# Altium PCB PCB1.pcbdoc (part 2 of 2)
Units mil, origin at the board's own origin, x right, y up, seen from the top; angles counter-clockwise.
Board outline 2869.57 x 2682.86 mil, 2 copper layers (Top Layer, Bottom Layer); 61 components, 43 nets, 230 pads, 47 vias.
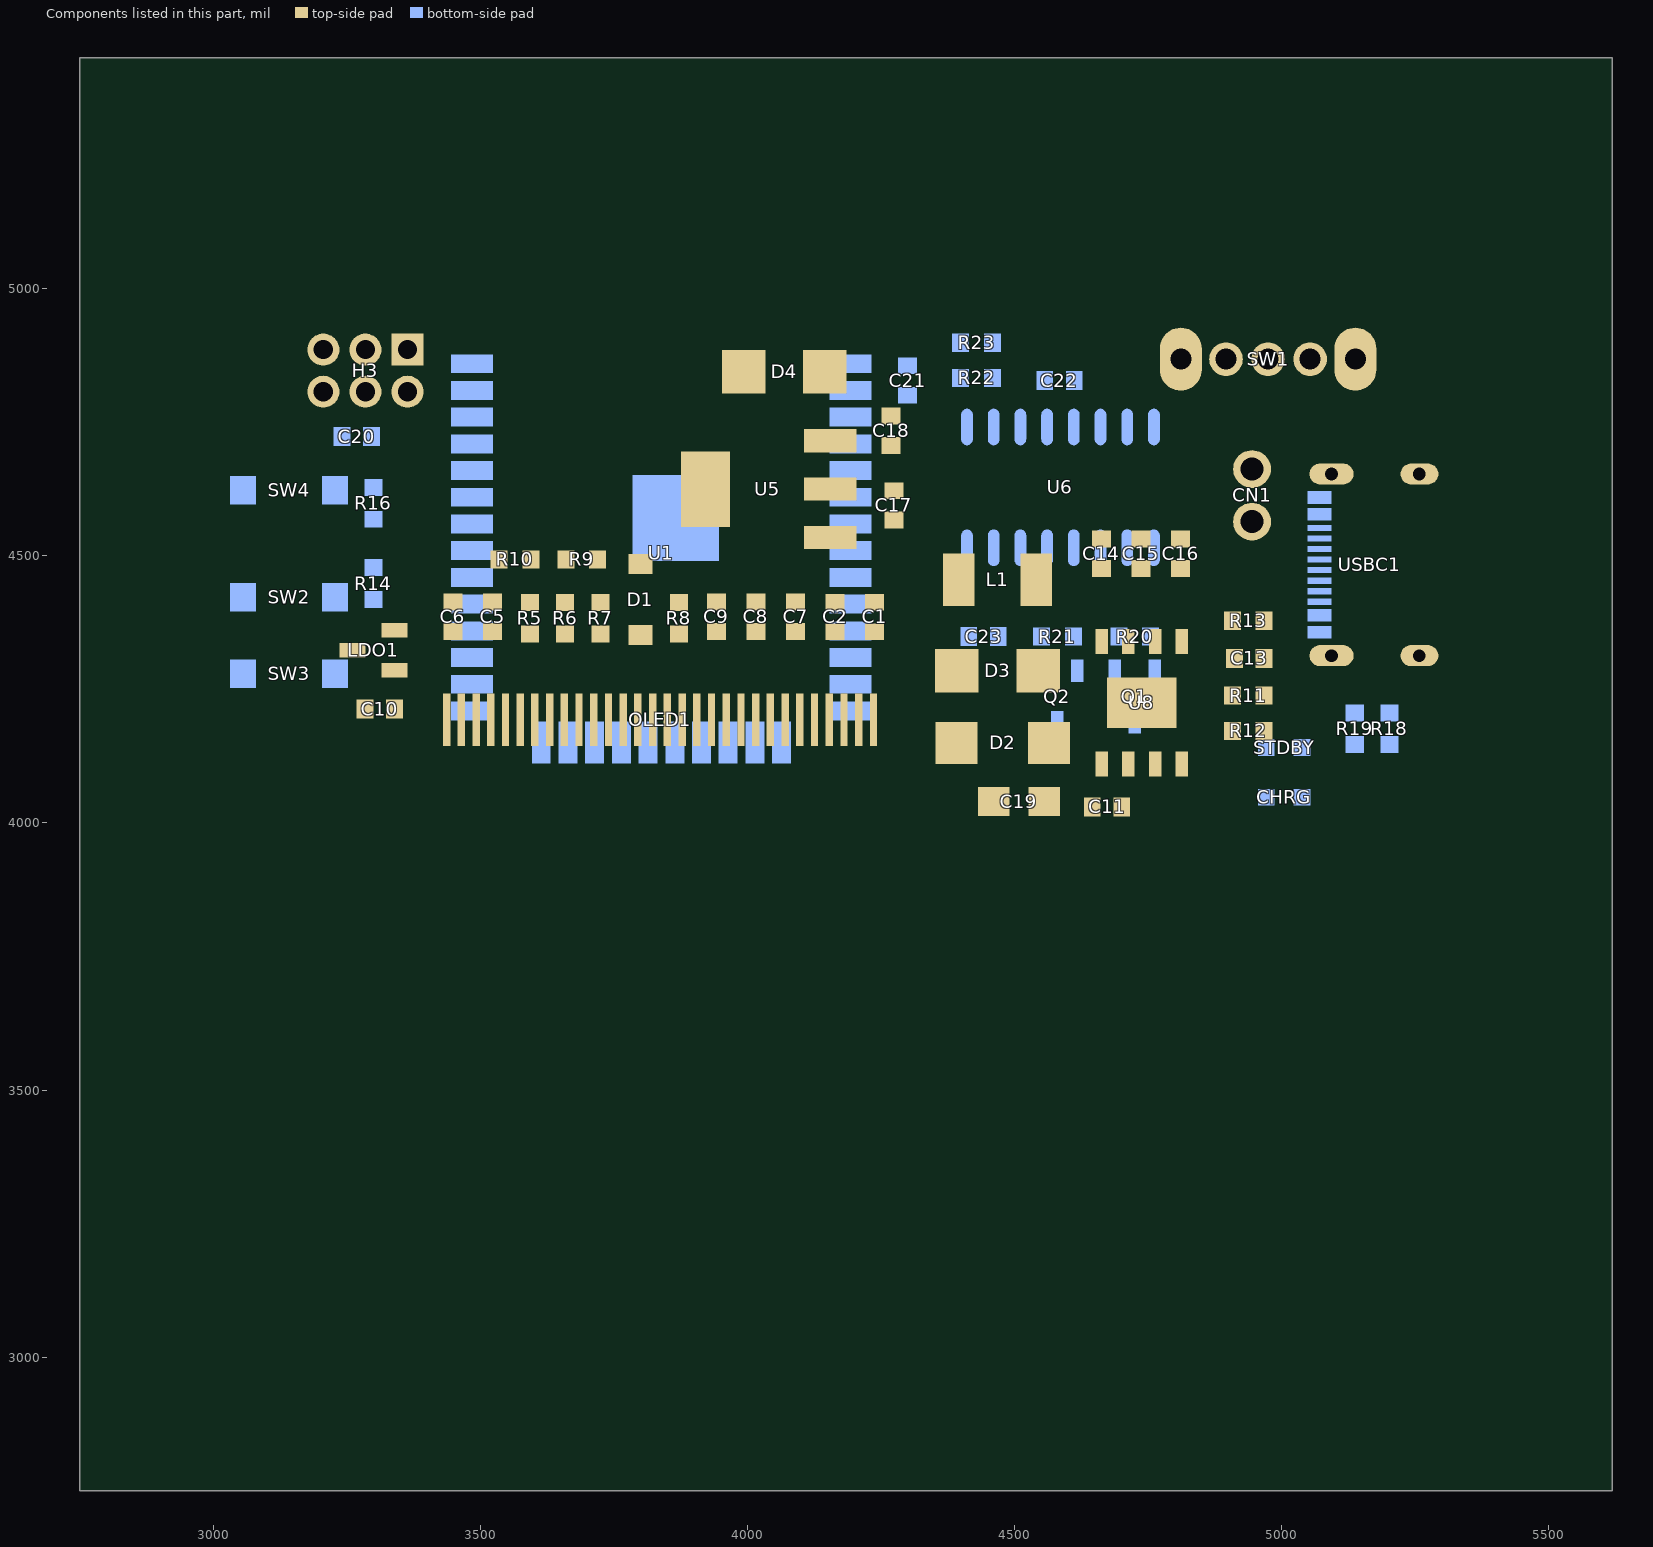
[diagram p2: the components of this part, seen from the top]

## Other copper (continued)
Bottom Layer:
  region net 3V3: 4262.95,4799.79 4262.95,4819.79 cw(c4262.95,5034.18) 4232.95,4821.9 4232.95,4797.68 cw(c4262.95,4585.4)
  region net EN: 4139.21,4758.33 4139.21,4748.33 cw(c4139.21,4727.21) 4154.21,4742.07 4154.21,4765.83 cw(c4139.21,4777.08)
  region net EN: 4247.95,4754.79 4247.95,4764.79 cw(c4247.95,4783.54) 4232.95,4772.29 4232.95,4747.29 cw(c4247.95,4736.04)
  region net IO32: 4143.54,4514.79 4143.54,4504.79 cw(c4143.54,4493.44) 4154.21,4497.29 4154.21,4522.29 cw(c4143.54,4526.13)
  region net IO33: 4143.61,4481.79 4143.61,4467.65 cw(c4118,4442.04) 4154.21,4442.07 4158.5,4477.5 cw(c4154.93,4493.11)
  region net IO2: 3581.54,4155.73 3581.54,4145.73 cw(c3581.54,4126.98) 3596.54,4138.23 3596.54,4163.23 cw(c3581.54,4174.48)
  region net IO0: 3539.29,4204.79 3539.29,4214.79 cw(c3539.29,4233.54) 3524.29,4222.29 3524.29,4197.29 cw(c3539.29,4186.04)
  region net IO0: 3430.55,4214.79 3430.55,4204.79 cw(c3430.55,4186.04) 3445.55,4197.29 3445.55,4222.29 cw(c3430.55,4233.54)
  region net SCL: 3528.82,4431.46 3534.9,4439.52 cw(c3561.42,4466.04) 3524.29,4460.74 3507.6,4442.07 cw(c3502.3,4404.95)
  region net RXD0: 3534.9,4676.15 3532.71,4688.11 cw(c3506.2,4714.63) 3511.5,4677.5 3524.29,4664.06 cw(c3621.68,4589.38)
  region net TXD0: 3536.46,4704.79 3536.46,4714.79 cw(c3536.46,4728.41) 3524.29,4722.29 3524.29,4697.29 cw(c3536.46,4691.17)
  region net $1N4419: 5043.5,4079.07 5033.5,4079.07 cw(c5014.75,4079.07) 5026,4064.07 5051,4064.07 cw(c5062.25,4079.07)
  region net $1N4369: 4940.75,4053.33 4940.75,4043.33 cw(c4940.75,4024.58) 4955.75,4035.83 4955.75,4060.83 cw(c4940.75,4072.08)
  region net 3V3: 3347.01,4558.33 3347.01,4578.33 cw(c3347.01,4653.83) 3317.01,4584.54 3317.01,4552.79 cw(c3347.01,4474.27)
  region net 3V3: 3290,4522.79 3310,4522.79 cw(c3524.39,4522.79) 3312.11,4552.79 3287.89,4552.79 cw(c3075.61,4522.79)
  region net EN: 3267.99,4632.99 3267.99,4622.99 cw(c3267.99,4604.24) 3282.99,4615.49 3282.99,4640.49 cw(c3267.99,4651.74)
  region net EN: 3332.01,4622.99 3332.01,4632.99 cw(c3332.01,4651.74) 3317.01,4640.49 3317.01,4615.49 cw(c3332.01,4604.24)
  region net $1N9758: 4465,4790.13 4455,4788.79 4454.8,4787.52 4450.32,4765.18 4450.27,4764.74 4472.32,4764.74 4472.24,4765.18
  region net $1N9782: 4516.29,4789.57 4506.29,4789.57 4506.23,4789.14 4500.83,4767.36 4500.34,4765.19 4500.27,4764.74 4522.32,4764.74 4522.25,4765.18 4516.85,4786.99 4516.36,4789.14
  region net $1N9477: 4566.29,4789.57 4556.29,4789.57 4556.36,4788.21 4556.53,4786.94 4556.79,4785.74 4557.26,4784.08 4558.22,4781.11 4558.44,4780.21 4558.52,4779.77 4558.57,4779.34 4558.59,4778.91 4558.58,4778.49 4558.53,4778.08 4558.44,4777.66 4558.3,4777.25 4558.12,4776.84 4557.89,4776.43 4557.6,4776.03 4557.26,4775.62 4556.85,4775.21 4556.38,4774.79 4555.85,4774.38 4555.24,4773.96 4567.35,4773.96 4566.74,4774.38 4566.2,4774.79 4565.74,4775.21 4565.33,4775.62 4564.99,4776.03 4564.7,4776.43 4564.47,4776.84 4564.29,4777.25 4564.15,4777.66 4564.06,4778.08 4564.01,4778.49 4564,4778.91 4564.02,4779.34 4564.07,4779.77 4564.24,4780.66 4564.65,4782.05 4565.65,4785.17 4565.94,4786.33 4566.16,4787.57 4566.28,4788.88
  region net D+: 4606.29,4693.27 4616.29,4693.27 4616.23,4694.62 4616.06,4695.89 4615.8,4697.09 4615.33,4698.76 4614.37,4701.72 4614.14,4702.62 4614.07,4703.06 4614.02,4703.49 4614,4703.92 4614.01,4704.34 4614.06,4704.76 4614.15,4705.17 4614.29,4705.58 4614.47,4705.99 4614.7,4706.4 4614.99,4706.81 4615.33,4707.22 4615.74,4707.63 4616.2,4708.04 4616.74,4708.46 4617.35,4708.88 4605.24,4708.88 4605.85,4708.46 4606.38,4708.04 4606.85,4707.63 4607.26,4707.22 4607.6,4706.81 4607.89,4706.4 4608.12,4705.99 4608.3,4705.58 4608.44,4705.17 4608.53,4704.76 4608.58,4704.34 4608.59,4703.92 4608.57,4703.49 4608.52,4703.06 4608.34,4702.18 4607.93,4700.78 4606.94,4697.66 4606.65,4696.5 4606.43,4695.27 4606.31,4693.95
  region net D-: 4656.29,4693.27 4666.29,4693.27 4666.23,4694.62 4666.06,4695.89 4665.8,4697.09 4665.33,4698.76 4664.37,4701.72 4664.14,4702.62 4664.07,4703.06 4664.02,4703.49 4664,4703.92 4664.01,4704.34 4664.06,4704.76 4664.15,4705.17 4664.29,4705.58 4664.47,4705.99 4664.7,4706.4 4664.99,4706.81 4665.33,4707.22 4665.74,4707.63 4666.2,4708.04 4666.74,4708.46 4667.35,4708.88 4655.24,4708.88 4655.85,4708.46 4656.38,4708.04 4656.85,4707.63 4657.26,4707.22 4657.6,4706.81 4657.89,4706.4 4658.12,4705.99 4658.3,4705.58 4658.44,4705.17 4658.53,4704.76 4658.58,4704.34 4658.59,4703.92 4658.57,4703.49 4658.52,4703.06 4658.34,4702.18 4657.93,4700.78 4656.94,4697.66 4656.65,4696.5 4656.43,4695.27 4656.31,4693.95
  region net +5V: 4421.29,4573.2 4401.29,4573.2 4400.27,4538.56 4422.32,4538.56
  region net +5V: 4401.29,4457.27 4421.29,4457.27 4421.26,4457.95 4421.18,4458.66 4421.04,4459.41 4420.62,4461.01 4419.73,4463.59 4416.78,4471 4415.85,4473.73 4415.39,4475.47 4415.23,4476.3 4415.11,4477.1 4415.05,4477.88 4415.05,4478.61 4415.12,4479.32 4415.25,4479.98 4415.46,4480.6 4415.75,4481.17 4416.13,4481.69 4416.59,4482.16 4417.15,4482.57 4405.43,4482.57 4406,4482.16 4406.46,4481.69 4406.84,4481.17 4407.13,4480.6 4407.34,4479.98 4407.47,4479.32 4407.54,4478.61 4407.54,4477.88 4407.48,4477.1 4407.36,4476.3 4406.99,4474.61 4406.46,4472.84 4405.08,4469.14 4402.53,4462.71 4401.97,4461.01 4401.55,4459.41 4401.41,4458.66 4401.32,4457.95
  region net RTS: 4506.29,4467.09 4516.29,4467.09 4516.23,4468.44 4516.06,4469.71 4515.8,4470.91 4515.33,4472.58 4514.37,4475.54 4514.14,4476.44 4514.07,4476.88 4514.02,4477.31 4514,4477.74 4514.01,4478.16 4514.06,4478.58 4514.15,4478.99 4514.29,4479.4 4514.47,4479.81 4514.7,4480.22 4514.99,4480.63 4515.33,4481.04 4515.74,4481.45 4516.2,4481.86 4516.74,4482.28 4517.35,4482.7 4505.24,4482.7 4505.85,4482.28 4506.38,4481.86 4506.85,4481.45 4507.26,4481.04 4507.6,4480.63 4507.89,4480.22 4508.12,4479.81 4508.3,4479.4 4508.44,4478.99 4508.53,4478.58 4508.58,4478.16 4508.59,4477.74 4508.57,4477.31 4508.52,4476.88 4508.34,4476 4507.93,4474.6 4506.94,4471.48 4506.65,4470.32 4506.43,4469.09 4506.31,4467.77
  region net DTR: 4556.29,4467.09 4566.29,4467.09 4566.23,4468.44 4566.06,4469.71 4565.8,4470.91 4565.33,4472.58 4564.37,4475.54 4564.14,4476.44 4564.07,4476.88 4564.02,4477.31 4564,4477.74 4564.01,4478.16 4564.06,4478.58 4564.15,4478.99 4564.29,4479.4 4564.47,4479.81 4564.7,4480.22 4564.99,4480.63 4565.33,4481.04 4565.74,4481.45 4566.2,4481.86 4566.74,4482.28 4567.35,4482.7 4555.24,4482.7 4555.85,4482.28 4556.38,4481.86 4556.85,4481.45 4557.26,4481.04 4557.6,4480.63 4557.89,4480.22 4558.12,4479.81 4558.3,4479.4 4558.44,4478.99 4558.53,4478.58 4558.58,4478.16 4558.59,4477.74 4558.57,4477.31 4558.52,4476.88 4558.34,4476 4557.93,4474.6 4556.94,4471.48 4556.65,4470.32 4556.43,4469.09 4556.31,4467.77
  region net V_USB: 5029.49,4398.84 5029.49,4378.84 cw(c5029.49,4273.3) 5048.96,4377.03 5048.96,4400.65 cw(c5029.49,4504.37)
  region net V_USB: 5034.49,4587.82 5034.49,4567.82 cw(c5034.49,4506.07) 5048.96,4566.1 5048.96,4589.54 cw(c5034.49,4649.56)
  region net D+: 5045,4458.8 5045,4448.8 cw(c5045,4439.7) 5048.96,4447.89 5048.96,4459.7 cw(c5045,4467.9)
  region net D-: 5100.16,4468.49 5100.16,4478.49 cw(c5100.16,4499.36) 5094.23,4479.35 5094.23,4467.63 cw(c5100.16,4447.62)
  region net D+: 5034.47,4498.17 5034.47,4488.17 cw(c5034.47,4371.81) 5048.96,4487.26 5048.96,4499.07 cw(c5034.47,4614.53)
  region net D-: 5033.96,4517.86 5033.96,4507.86 cw(c5033.96,4383.16) 5048.96,4506.95 5048.96,4518.76 cw(c5033.96,4642.55)
  region net D-: 5100.47,4507.86 5100.47,4517.86 cw(c5100.47,4539.79) 5094.23,4518.76 5094.23,4506.95 cw(c5100.47,4485.92)
  region net $1N9366: 5109.23,4527.54 5109.23,4537.54 cw(c5109.23,4668.87) 5094.23,4538.4 5094.23,4526.68 cw(c5109.23,4396.2)
  region net 3V3: 4317.93,4768.7 4332.07,4782.84 ccw(c4323.41,4774.18) 4317.72,4785.02 4282.28,4785.02 cw(c4278.16,4728.92)
  region net $1N9366: 5207.18,4236.76 5197.18,4236.76 cw(c5178.43,4236.76) 5189.68,4221.76 5214.68,4221.76 cw(c5225.93,4236.76)
  region net $1N17323: 5158.54,4220.17 5151.46,4227.24 cw(c5137.85,4240.86) 5135.38,4221.76 5154.19,4205.22 cw(c5169.97,4208.74)
  region net $1N9680: 4693.26,4321.45 4683.26,4321.45 cw(c4663.34,4321.45) 4676.45,4306.45 4700.08,4306.45 cw(c4713.19,4321.45)
  region net RTS: 4740.65,4270.04 4740.65,4255.9 cw(c4761.07,4235.48) 4759.68,4264.33 4751.25,4291.26 cw(c4714.13,4296.56)
  region net EN: 4698.85,4193.14 4698.85,4183.14 cw(c4698.85,4164.39) 4713.85,4175.64 4713.85,4200.64 cw(c4698.85,4211.89)
  region net $1N9678: 4548.26,4321.45 4538.26,4321.45 cw(c4518.34,4321.45) 4531.45,4306.45 4555.08,4306.45 cw(c4568.19,4321.45)
  region net IO0: 4558.25,4172.79 4559.39,4159.79 cw(c4576.98,4142.2) 4577.28,4167.08 4568.85,4194.01 cw(c4531.73,4199.31)
  region net $1N9680: 4683.26,4317.08 4693.26,4317.08 cw(c4712.01,4317.08) 4700.76,4332.08 4682.21,4332.08 cw(c4576.07,4317.08)
  region net DTR: 4733.7,4376.7 4728.84,4367.41 cw(c4702.33,4340.9) 4739.45,4346.2 4754.91,4366.09 cw(c4760.21,4403.22)
  region net DTR: 4779.78,4321.47 4781.81,4333.59 cw(c4808.32,4360.11) 4771.2,4354.8 4758.57,4332.08 cw(c4753.27,4294.95)
  region net $1N9678: 4538.26,4317.08 4548.26,4317.08 cw(c4567.01,4317.08) 4555.76,4332.08 4537.21,4332.08 cw(c4431.07,4317.08)
  region net RTS: 4593.7,4376.7 4583.84,4372.41 cw(c4557.33,4345.9) 4594.45,4351.2 4614.91,4366.09 cw(c4620.21,4403.22)
  region net RTS: 4630.87,4321.47 4636.81,4329.67 cw(c4663.32,4356.19) 4626.2,4350.89 4609.65,4332.08 cw(c4604.35,4294.95)
  region net $1N9758: 4455,4801.22 4465,4801.22 cw(c4483.75,4801.22) 4472.5,4816.22 4447.5,4816.22 cw(c4436.25,4801.22)
  region net RXD0: 4379.56,4860.84 4373.08,4853.18 cw(c4346.56,4826.66) 4383.69,4831.96 4400.77,4850.23 cw(c4406.07,4887.36)
  region net $1N9782: 4479.42,4871.63 4485.36,4879.83 cw(c4511.88,4906.35) 4474.76,4901.04 4458.21,4882.23 cw(c4452.91,4845.11)
  region net TXD0: 4379.02,4926.86 4373.08,4918.65 cw(c4346.56,4892.14) 4383.69,4897.44 4400.23,4916.25 cw(c4405.53,4953.37)
  region net $1N9477: 4556.29,4795.61 4566.29,4795.61 cw(c4587.27,4795.61) 4572.61,4810.61 4548.79,4810.61 cw(c4537.54,4795.61)
  region net +5V: 4421.29,4396.7 4401.29,4396.7 cw(c4205.98,4396.7) 4398.98,4366.7 4430.47,4366.7 cw(c4474.91,4396.7)
  region net IO0: 3267.24,4412.99 3267.24,4422.99 cw(c3267.24,4441.74) 3252.24,4430.49 3252.24,4405.49 cw(c3267.24,4394.24)
  region net 3V3: 3310,4523.86 3290,4523.86 cw(c3222.28,4523.86) 3282.99,4493.86 3317.01,4493.86 cw(c3377.72,4523.86)
  region net IO0: 3267.99,4422.99 3267.99,4412.99 cw(c3267.99,4394.24) 3282.99,4405.49 3282.99,4430.49 cw(c3267.99,4441.74)
  region net IO2: 3223.03,4237.35 3233.03,4237.35 cw(c3251.78,4237.35) 3240.53,4252.35 3215.53,4252.35 cw(c3204.28,4237.35)
  region net EN: 3233.03,4665.1 3223.03,4665.1 cw(c3204.28,4665.1) 3215.53,4650.1 3240.53,4650.1 cw(c3251.78,4665.1)
  region net EN: 3267.24,4622.99 3267.24,4632.99 cw(c3267.24,4651.74) 3252.24,4640.49 3252.24,4615.49 cw(c3267.24,4604.24)
  region net $1N4419: 5043.5,4171.89 5033.5,4171.89 cw(c5014.75,4171.89) 5026,4156.89 5051,4156.89 cw(c5062.25,4171.89)
  region net $1N4419: 5033.5,4110.39 5043.5,4110.39 cw(c5062.25,4110.39) 5051,4125.39 5026,4125.39 cw(c5014.75,4110.39)
  region net $1N4372: 4945.15,4121.86 4952.22,4114.79 cw(c4978.73,4088.27) 4973.43,4125.39 4955.75,4143.07 cw(c4918.63,4148.37)
  region net +5V: 3404.35,4919.79 3397.28,4926.86 cw(c3370.76,4953.37) 3376.06,4916.25 3393.74,4898.57 cw(c3430.86,4893.27)
  region net SDA: 3715,4314.66 3705,4314.66 3704.98,4314.1 3704.91,4313.53 3704.8,4312.96 3704.66,4312.39 3704.48,4311.83 3704.02,4310.72 3703.46,4309.65 3702.81,4308.61 3702.11,4307.62 3701,4306.26 3719,4306.26 3717.89,4307.62 3717.19,4308.61 3716.54,4309.65 3715.98,4310.72 3715.52,4311.83 3715.34,4312.39 3715.2,4312.96 3715.09,4313.53 3715.02,4314.1
  region net SCL: 3753.66,4278.33 3753.66,4268.33 3754.23,4268.3 3754.8,4268.24 3755.37,4268.13 3755.93,4267.98 3756.49,4267.8 3757.6,4267.35 3758.68,4266.78 3759.72,4266.14 3760.7,4265.44 3762.06,4264.33 3762.06,4282.33 3760.7,4281.21 3759.72,4280.51 3758.68,4279.87 3757.6,4279.31 3756.49,4278.85 3755.93,4278.67 3755.37,4278.52 3754.8,4278.42 3754.23,4278.35
  region net V_USB: 5017.37,4386.82 5031.51,4400.96 5030.32,4402.05 5028.11,4403.8 5027.14,4404.62 5026.71,4405.04 5026.32,4405.49 5025.97,4405.98 5025.66,4406.51 5025.4,4407.09 5025.2,4407.74 5025.06,4408.46 5024.97,4409.27 5009.06,4393.36 5009.87,4393.27 5010.59,4393.12 5011.24,4392.92 5011.82,4392.67 5012.35,4392.36 5012.83,4392.01 5013.29,4391.61 5013.71,4391.18 5014.52,4390.22 5016.28,4388.01
  region net V_USB: 5031.51,4560.7 5017.37,4574.84 5016.28,4573.65 5014.52,4571.43 5013.71,4570.47 5013.29,4570.04 5012.83,4569.64 5012.35,4569.29 5011.82,4568.99 5011.24,4568.73 5010.59,4568.53 5009.87,4568.38 5009.06,4568.3 5024.97,4552.39 5025.06,4553.19 5025.2,4553.91 5025.4,4554.56 5025.66,4555.15 5025.97,4555.68 5026.32,4556.16 5026.71,4556.61 5027.14,4557.04 5028.11,4557.85 5030.32,4559.6
  region net $1N4419: 5033.5,4201.99 5043.5,4201.99 5043.52,4202.56 5043.59,4203.13 5043.7,4203.69 5043.84,4204.26 5044.02,4204.82 5044.48,4205.93 5045.04,4207.01 5045.69,4208.05 5046.39,4209.03 5047.5,4210.39 5029.5,4210.39 5030.61,4209.03 5031.31,4208.05 5031.96,4207.01 5032.52,4205.93 5032.98,4204.82 5033.16,4204.26 5033.3,4203.69 5033.41,4203.13 5033.48,4202.56
  region net $1N4369: 4926.34,4043.33 4926.34,4053.33 4925.77,4053.35 4925.2,4053.42 4924.63,4053.52 4924.07,4053.67 4923.51,4053.85 4922.4,4054.31 4921.32,4054.87 4920.28,4055.51 4919.3,4056.21 4917.94,4057.33 4917.94,4039.33 4919.3,4040.44 4920.28,4041.14 4921.32,4041.78 4922.4,4042.35 4923.51,4042.8 4924.07,4042.98 4924.63,4043.13 4925.2,4043.24 4925.77,4043.3
  region net $1N4372: 4936.34,4103.33 4936.34,4113.33 4935.77,4113.35 4935.2,4113.42 4934.63,4113.52 4934.07,4113.67 4933.51,4113.85 4932.4,4114.31 4931.32,4114.87 4930.28,4115.51 4929.3,4116.21 4927.94,4117.33 4927.94,4099.33 4929.3,4100.44 4930.28,4101.14 4931.32,4101.78 4932.4,4102.35 4933.51,4102.8 4934.07,4102.98 4934.63,4103.13 4935.2,4103.24 4935.77,4103.3
  region net +5V: 4401.29,4602.9 4421.29,4602.9 4421.27,4603.44 4421.14,4604.68 4420.62,4608.4 4420.5,4609.91 4420.49,4610.62 4420.52,4611.3 4420.61,4611.93 4420.75,4612.49 4420.96,4612.99 4421.25,4613.4 4398.75,4613.4 4399.19,4612.86 4399.58,4612.29 4399.92,4611.7 4400.21,4611.1 4400.46,4610.47 4400.66,4609.83 4400.83,4609.18 4401.07,4607.83 4401.21,4606.45 4401.29,4603.62
  region net 3V3: 3359.58,4578.33 3359.58,4558.33 3361.19,4558.4 3364,4558.72 3365.25,4558.83 3365.86,4558.83 3366.46,4558.79 3367.05,4558.7 3367.64,4558.54 3368.23,4558.31 3368.84,4557.99 3369.45,4557.59 3370.08,4557.08 3370.08,4579.58 3369.45,4579.07 3368.84,4578.66 3368.23,4578.35 3367.64,4578.11 3367.05,4577.96 3366.46,4577.86 3365.86,4577.82 3365.25,4577.83 3364,4577.93 3361.19,4578.26
  region net EN: 3831.34,4748.33 3831.34,4758.33 3830.77,4758.35 3830.2,4758.42 3829.63,4758.52 3829.07,4758.67 3828.51,4758.85 3827.4,4759.31 3826.32,4759.87 3825.28,4760.51 3824.3,4761.21 3822.94,4762.33 3822.94,4744.33 3824.3,4745.44 3825.28,4746.14 3826.32,4746.78 3827.4,4747.35 3828.51,4747.8 3829.07,4747.98 3829.63,4748.13 3830.2,4748.24 3830.77,4748.3
  region net EN: 3343.66,4632.99 3343.66,4622.99 3344.19,4622.97 3344.73,4622.9 3345.29,4622.81 3345.85,4622.67 3346.99,4622.31 3348.12,4621.84 3349.22,4621.29 3350.26,4620.67 3351.22,4620.01 3352.06,4619.33 3352.06,4637.33 3350.17,4635.73 3349.19,4635 3348.17,4634.34 3347.65,4634.05 3347.11,4633.79 3346.57,4633.56 3346.01,4633.36 3345.45,4633.2 3344.86,4633.08 3344.27,4633.01
  region net IO32: 3701.34,4713.33 3701.34,4723.33 3700.77,4723.35 3700.2,4723.42 3699.63,4723.52 3699.07,4723.67 3698.51,4723.85 3697.4,4724.31 3696.32,4724.87 3695.28,4725.51 3694.3,4726.21 3692.94,4727.33 3692.94,4709.33 3694.3,4710.44 3695.28,4711.14 3696.32,4711.78 3697.4,4712.35 3698.51,4712.8 3699.07,4712.98 3699.63,4713.13 3700.2,4713.24 3700.77,4713.3
  region net IO33: 3666.34,4688.33 3666.34,4698.33 3665.77,4698.35 3665.2,4698.42 3664.63,4698.52 3664.07,4698.67 3663.51,4698.85 3662.4,4699.31 3661.32,4699.87 3660.28,4700.51 3659.3,4701.21 3657.94,4702.33 3657.94,4684.33 3659.3,4685.44 3660.28,4686.14 3661.32,4686.78 3662.4,4687.35 3663.51,4687.8 3664.07,4687.98 3664.63,4688.13 3665.2,4688.24 3665.77,4688.3
  region net 3V3: 4335,4643.75 4315,4643.75 4315.07,4642.13 4315.4,4639.33 4315.5,4638.07 4315.51,4637.47 4315.47,4636.87 4315.37,4636.28 4315.21,4635.69 4314.98,4635.09 4314.67,4634.49 4314.26,4633.88 4313.75,4633.25 4336.25,4633.25 4335.74,4633.88 4335.33,4634.49 4335.02,4635.09 4334.79,4635.69 4334.63,4636.28 4334.53,4636.87 4334.49,4637.47 4334.5,4638.07 4334.6,4639.33 4334.93,4642.13
  region net +5V: 3529.58,4928.33 3529.58,4918.33 3530.44,4918.29 3531.24,4918.19 3532,4918.02 3532.71,4917.79 3533.39,4917.51 3534.04,4917.17 3534.67,4916.79 3535.27,4916.37 3536.44,4915.43 3539.43,4912.66 3540.08,4912.08 3540.08,4934.58 3537.02,4931.74 3535.86,4930.74 3535.27,4930.28 3534.67,4929.86 3534.04,4929.48 3533.39,4929.15 3532.71,4928.86 3532,4928.64 3531.24,4928.47 3530.44,4928.36

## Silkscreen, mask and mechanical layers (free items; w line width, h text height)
Top Silkscreen Layer:
  lines w10 net "": 3160,4743.33 3165,4743.33 ; 3241.2,4604.17 3241.2,4743.33 ; 3241.2,4673.75 3319.69,4673.75 ; 3319.69,4603.35 3319.69,4743.33 ; 3849.39,4953.33 3849.39,4523.93 3895,4478.33 4252.03,4478.33 4302.46,4427.89 4302.46,3969.07 ; 3165,4743.33 3395,4743.33 3395,4603.33 3160,4603.33 3160,4738.33 3165,4743.33
  text "ON" at 4703.79,4938.34 h29.2 r180
  text "32" at 3264.99,4739.54 h29.2 r270
  text "GND" at 3189.99,4715.82 h29.2 r270
  text "GND" at 4859.99,4710.82 h29.2 r270
  text "5V" at 3344.99,4699.54 h29.2 r270
  text "33" at 3264.99,4664.54 h29.2 r270
  text "BAT" at 4859.99,4605.82 h29.2 r270
  text "0" at 3480,4503.21 h29.42
  text "1" at 3751.48,4503.21 h29.42
  text "address select" at 3752.81,3343.32 h29.2
Bottom Silkscreen Layer:
  text "ON" at 4763.79,4938.34 h29.2 r180
  text "EN" at 3108.79,4693.32 h29.2
  text "IO0" at 3122.51,4493.32 h29.2
  text "IO2" at 3122.51,4183.32 h29.2
  text "Congratulations on my graduation. /  by Yem /  230705" at 4790.49,4034.99 h22.36
Mechanical Layer:
  circle w1 net "": c3083.74,4874.59 r59.06
  circle w1 net "": c5288.46,4874.59 r59.06
  circle w1 net "": c5288.46,4047.81 r59.06
  circle w1 net "": c3083.74,4047.81 r59.06
  lines w1 net "": 3406.18,3969.07 4272.32,3969.07 4272.32,4028.13 3406.18,4028.13 3406.18,3969.07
